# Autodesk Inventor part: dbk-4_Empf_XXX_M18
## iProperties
Shininess: 20.0
Length Units: 11269
Angle Units: 11279
Time Units: 11290
Mass Units: 11283
Length Display Precision: 2
Angle Display Precision: 2
Part Number: dbk-4_Empf_XXX_M18
Material: Nichtrostender Stahl - 440C
Document SubType Name: Modellieren
Description: dbk-4/Empf/XXX/M18
Checked By: Alves
Created: 2005-08
Designer: Ohle
Manufacturer: Standard
Standards Organization: Custom
Density: 0.0
Volumn: 0.0
Area: 0.0
PropertySet Name: Model Information
Control State: 0
Master: False
Checked Out: False
Last Check In By: Tanck
Last Check In Date: 2005-08-10
BESTELLNUMMER: dbk-4/Empf/XXX/M18
ME: ST
Title: dbk-4 Sensoren
Author: Ohle
Comments: keine Bemerkung
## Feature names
1. dbk-4 Empfänger [Revolution]
2. Kabel GK [Extrusion]
3. LED [Revolution]
